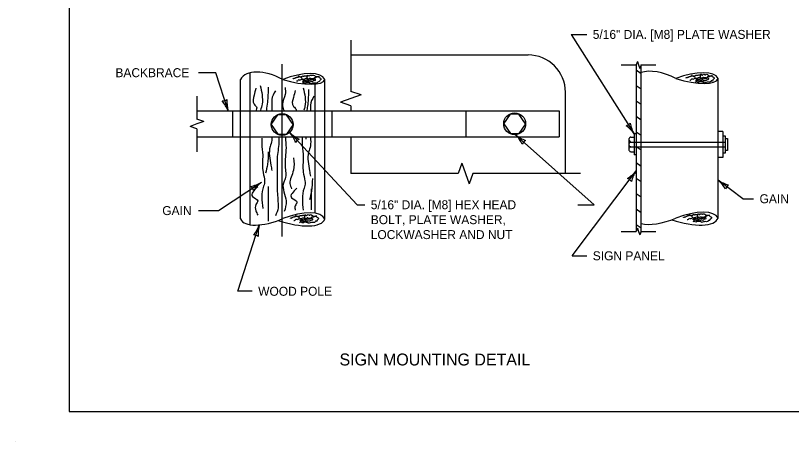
# Model space of a CAD drawing. Extents: x 49991.4 to 50021, y 49987.6 to 50011.4.
# Drawn here: x 49999.98 to 50005.17, y 49999.86 to 50002.71 of the extents above; entities that cross this region are included whole.
import ezdxf

# ---------------------------------------------------------------- set-up
doc = ezdxf.new("R2010")
doc.units = 0
for name, color, linetype in [('Level 1', 7, 'Continuous'), ('Level 2', 7, 'Continuous'), ('Level 3', 7, 'Continuous'), ('Level 4', 7, 'Continuous'), ('Level 5', 7, 'Continuous'), ('Level 6', 7, 'Continuous')]:
    doc.layers.add(name, color=color, linetype=linetype)

msp = doc.modelspace()

# ---------------------------------------------------------------- linework, layer by layer
at = {"layer": 'Level 1'}
for p, q in [((50002.2226, 50002.4506), (50003.4105, 50002.4506)), ((50001.5488, 50002.0757), (50001.5488, 50002.3308)), ((50004.1671, 50002.3252), (50004.1345, 50002.3481)), ((50001.4839, 50002.0757), (50001.4839, 50002.2867)), ((50002.0488, 50002.0757), (50002.0488, 50002.2867)), ((50004.6826, 50001.3581), (50004.6826, 50002.2926)), ((50001.9839, 50002.0757), (50001.9839, 50002.2554)), ((50004.1671, 50002.2217), (50004.1345, 50002.2446)), ((50003.6605, 50001.6566), (50003.6605, 50002.2006)), ((50004.1671, 50002.1183), (50004.1345, 50002.1412)), ((50001.1917, 50002.0757), (50003.6179, 50002.0757)), ((50001.4304, 50002.0757), (50001.4304, 50001.9014)), ((50002.0955, 50002.0757), (50002.0955, 50001.9014)), ((50002.9941, 50002.0757), (50002.9941, 50001.9014)), ((50003.6179, 50002.0757), (50003.6179, 50001.9014)), ((50001.6896, 50001.9851), (50001.7349, 50002.05)), ((50001.7913, 50002.05), (50001.7349, 50002.05)), ((50001.8366, 50001.9851), (50001.7913, 50002.05)), ((50003.2468, 50001.9897), (50003.2921, 50002.0546)), ((50003.3485, 50002.0546), (50003.2921, 50002.0546)), ((50003.3938, 50001.9897), (50003.3485, 50002.0546)), ((50004.1671, 50002.0148), (50004.1345, 50002.0377)), ((50001.6896, 50001.9851), (50001.7349, 50001.9202)), ((50001.8366, 50001.9851), (50001.7913, 50001.9202)), ((50003.2468, 50001.9897), (50003.2921, 50001.9248)), ((50003.3938, 50001.9897), (50003.3485, 50001.9248)), ((50001.7349, 50001.9202), (50001.7913, 50001.9202)), ((50003.2921, 50001.9248), (50003.3485, 50001.9248)), ((50004.1214, 50001.9215), (50004.1214, 50001.7823)), ((50004.1345, 50001.9215), (50004.1214, 50001.9215)), ((50004.1671, 50001.9114), (50004.1345, 50001.9343)), ((50004.716, 50001.9384), (50004.6826, 50001.9384)), ((50004.716, 50001.9384), (50004.716, 50001.7642)), ((50004.7325, 50001.9078), (50004.716, 50001.9078)), ((50004.7325, 50001.795), (50004.7325, 50001.9078)), ((50001.1917, 50001.9014), (50003.6179, 50001.9014)), ((50001.4839, 50001.3523), (50001.4839, 50001.9014)), ((50001.5488, 50001.3137), (50001.5488, 50001.9014)), ((50001.9211, 50001.8982), (50001.9219, 50001.886)), ((50001.9839, 50001.3907), (50001.9839, 50001.9014)), ((50002.0488, 50001.3523), (50002.0488, 50001.9014)), ((50004.0885, 50001.8114), (50004.0885, 50001.8912)), ((50004.0885, 50001.8676), (50004.1214, 50001.8676)), ((50004.0979, 50001.9004), (50004.1214, 50001.9004)), ((50004.0885, 50001.8351), (50004.1214, 50001.8351)), ((50004.098, 50001.8028), (50004.1214, 50001.8028)), ((50004.1671, 50001.8128), (50004.1345, 50001.8357)), ((50004.1345, 50001.7823), (50004.1214, 50001.7823)), ((50004.716, 50001.7642), (50004.6826, 50001.7642)), ((50004.716, 50001.795), (50004.7325, 50001.795)), ((50004.1671, 50001.7045), (50004.1345, 50001.7274)), ((50004.1671, 50001.601), (50004.1345, 50001.6239)), ((50004.1671, 50001.4976), (50004.1345, 50001.5205)), ((50004.1671, 50001.3944), (50004.1345, 50001.4173)), ((50004.1671, 50001.2904), (50004.1345, 50001.3133)), ((49999.9766, 49999.8624), (49999.9766, 49999.8624))]:
    msp.add_line(p, q, dxfattribs=at)
for points in [[(50008.6146, 50011.2628), (50000.3356, 50011.2628), (50000.3356, 50000.0624), (50008.6146, 50000.0624)], [(50004.7325, 50001.892), (50004.7452, 50001.892), (50004.7452, 50001.8102), (50004.7325, 50001.8102)]]:
    msp.add_lwpolyline(points, close=True, dxfattribs=at)
for points in [[(50004.1345, 50002.3834), (50004.1345, 50001.2689)], [(50004.1671, 50001.2689), (50004.1671, 50002.3834)]]:
    msp.add_lwpolyline(points, dxfattribs=at)
for centre in [(50003.3203, 50001.9897), (50001.7631, 50001.9851)]:
    msp.add_circle(centre, 0.0735, dxfattribs=at)
for centre, radius, start, end in [((50003.4105, 50002.2006), 0.25, 0, 90), ((50004.0978, 50001.8911), 0.0093, 89.3839, 179.3839), ((50004.0978, 50001.877), 0.00933, 180.3852, 270.3852), ((50004.0978, 50001.8583), 0.00929, 89.3617, 179.3617), ((50004.0979, 50001.8445), 0.00937, 181.6734, 271.6734), ((50004.0979, 50001.8257), 0.00942, 89.9897, 179.9897), ((50004.0976, 50001.8119), 0.00906, 182.8466, 272.8466)]:
    msp.add_arc(centre, radius, start, end, dxfattribs=at)
for centre, major_axis, ratio, start_param, end_param in [((50001.7031, 50002.169), (-0.2192, 0.1177), 0.537084, 4.712389, 6.283185), ((50001.8031, 50002.1916), (0.2457, 0.0951), 0.387082, 0, 1.570796), ((50004.3369, 50002.1748), (-0.2192, 0.1177), 0.537084, 4.712389, 5.832755), ((50004.4369, 50002.1975), (0.2457, 0.0951), 0.387082, 0, 1.570796), ((50001.7903, 50002.3655), (0.2585, -0.0788), 0.304673, 4.712389, 6.283185), ((50004.4241, 50002.3713), (0.2585, -0.0788), 0.304673, 4.712389, 6.283185), ((50001.8031, 50001.2572), (0.2457, 0.0951), 0.395997, 0, 1.56463), ((50004.4369, 50001.263), (0.2457, 0.0951), 0.387082, 0, 1.570796), ((50001.7235, 50001.4559), (-0.2396, -0.1036), 0.420526, 0, 1.570599), ((50001.7722, 50001.45), (0.2766, -0.0977), 0.384401, 4.720139, 6.283185), ((50004.3572, 50001.4617), (-0.2396, -0.1036), 0.429269, 0.492318, 1.564034), ((50004.406, 50001.4559), (0.2766, -0.0977), 0.384401, 4.732241, 6.283185)]:
    msp.add_ellipse(centre, major_axis=major_axis, ratio=ratio, start_param=start_param, end_param=end_param, dxfattribs=at)
for points in [[(50004.4697, 50002.2957), (50004.4697, 50002.2986), (50004.4755, 50002.2986), (50004.4798, 50002.3015), (50004.4842, 50002.3015), (50004.4885, 50002.3059), (50004.4928, 50002.3059), (50004.4986, 50002.3087), (50004.5029, 50002.3087), (50004.5115, 50002.3116), (50004.5202, 50002.3073), (50004.5245, 50002.3116), (50004.5303, 50002.3116), (50004.5346, 50002.3159), (50004.5418, 50002.3145), (50004.5461, 50002.3159), (50004.5505, 50002.3159), (50004.5563, 50002.3174), (50004.5605, 50002.3174), (50004.5663, 50002.3188), (50004.5735, 50002.3188), (50004.5735, 50002.3159), (50004.5778, 50002.3159), (50004.5836, 50002.3202), (50004.5923, 50002.3202), (50004.5966, 50002.3174), (50004.6009, 50002.3202), (50004.6124, 50002.3188), (50004.6226, 50002.3116), (50004.6341, 50002.3116), (50004.6398, 50002.3101), (50004.6441, 50002.3059), (50004.6528, 50002.3015), (50004.6571, 50002.2943), (50004.6557, 50002.2914), (50004.6485, 50002.2842), (50004.6427, 50002.2756), (50004.6398, 50002.2784), (50004.6341, 50002.2727), (50004.6268, 50002.2683), (50004.6182, 50002.2683), (50004.6023, 50002.2669), (50004.588, 50002.2626)], [(50004.562, 50002.29), (50004.5663, 50002.3001), (50004.5635, 50002.3073), (50004.5678, 50002.3159), (50004.5706, 50002.3231)], [(50001.836, 50002.2899), (50001.836, 50002.2928), (50001.8417, 50002.2928), (50001.846, 50002.2957), (50001.8504, 50002.2957), (50001.8547, 50002.3), (50001.859, 50002.3), (50001.8648, 50002.3029), (50001.8691, 50002.3029), (50001.8778, 50002.3057), (50001.8864, 50002.3015), (50001.8908, 50002.3057), (50001.8965, 50002.3057), (50001.9008, 50002.3101), (50001.9081, 50002.3087), (50001.9123, 50002.3101), (50001.9167, 50002.3101), (50001.9225, 50002.3115), (50001.9268, 50002.3115), (50001.9326, 50002.313), (50001.9398, 50002.313), (50001.9398, 50002.3101), (50001.9441, 50002.3101), (50001.9498, 50002.3144), (50001.9585, 50002.3144), (50001.9628, 50002.3115), (50001.9671, 50002.3144), (50001.9786, 50002.313), (50001.9888, 50002.3057), (50002.0003, 50002.3057), (50002.0061, 50002.3043), (50002.0104, 50002.3), (50002.019, 50002.2957), (50002.0234, 50002.2885), (50002.0219, 50002.2856), (50002.0147, 50002.2784), (50002.0089, 50002.2697), (50002.0061, 50002.2726), (50002.0003, 50002.2669), (50001.9931, 50002.2625), (50001.9844, 50002.2625), (50001.9686, 50002.2611), (50001.9542, 50002.2567)], [(50001.859, 50002.277), (50001.8677, 50002.2784), (50001.8735, 50002.2856), (50001.8821, 50002.2827), (50001.8908, 50002.287), (50001.9037, 50002.2885), (50001.9138, 50002.2914), (50001.934, 50002.2928), (50001.9426, 50002.2885), (50001.947, 50002.2957), (50001.9527, 50002.2942), (50001.9613, 50002.2928), (50001.97, 50002.2928), (50001.9715, 50002.2885), (50001.9772, 50002.2914), (50001.9816, 50002.2914), (50001.9844, 50002.2827), (50001.9816, 50002.2784), (50001.9772, 50002.2798), (50001.9715, 50002.277), (50001.9657, 50002.2712), (50001.9527, 50002.2741), (50001.9441, 50002.2654), (50001.9326, 50002.264), (50001.9268, 50002.264), (50001.9181, 50002.2597), (50001.9095, 50002.264), (50001.8965, 50002.2611)], [(50001.9138, 50002.2784), (50001.8965, 50002.2914), (50001.8908, 50002.2986), (50001.8763, 50002.3057), (50001.8705, 50002.3115)], [(50001.9023, 50002.2798), (50001.9081, 50002.2812), (50001.9181, 50002.2827), (50001.921, 50002.2798), (50001.9268, 50002.2827), (50001.934, 50002.2827), (50001.9368, 50002.2683), (50001.9311, 50002.2726), (50001.9268, 50002.2697), (50001.9196, 50002.2697), (50001.9123, 50002.2741), (50001.9037, 50002.2726), (50001.9008, 50002.2755), (50001.8994, 50002.2784)], [(50001.9282, 50002.2842), (50001.9326, 50002.2942), (50001.9297, 50002.3015), (50001.934, 50002.3101), (50001.9368, 50002.3173)], [(50001.9383, 50002.2683), (50001.9484, 50002.2625), (50001.9571, 50002.2625)], [(50001.9426, 50002.2784), (50001.9484, 50002.2842), (50001.9599, 50002.287), (50001.9729, 50002.2885), (50001.9816, 50002.3), (50001.9873, 50002.3), (50001.9916, 50002.3015), (50002.0017, 50002.3057), (50002.0119, 50002.3072)], [(50004.4928, 50002.2828), (50004.5015, 50002.2842), (50004.5072, 50002.2914), (50004.5159, 50002.2886), (50004.5245, 50002.2929), (50004.5375, 50002.2943), (50004.5476, 50002.2972), (50004.5678, 50002.2986), (50004.5764, 50002.2943), (50004.5808, 50002.3015), (50004.5865, 50002.3001), (50004.5951, 50002.2986), (50004.6038, 50002.2986), (50004.6053, 50002.2943), (50004.611, 50002.2972), (50004.6153, 50002.2972), (50004.6182, 50002.2886), (50004.6153, 50002.2842), (50004.611, 50002.2856), (50004.6053, 50002.2828), (50004.5995, 50002.277), (50004.5865, 50002.2799), (50004.5778, 50002.2713), (50004.5663, 50002.2698), (50004.5605, 50002.2698), (50004.5519, 50002.2655), (50004.5433, 50002.2698), (50004.5303, 50002.2669)], [(50004.5476, 50002.2842), (50004.5303, 50002.2972), (50004.5245, 50002.3044), (50004.5101, 50002.3116), (50004.5043, 50002.3174)], [(50004.536, 50002.2856), (50004.5418, 50002.2871), (50004.5519, 50002.2886), (50004.5548, 50002.2856), (50004.5605, 50002.2886), (50004.5678, 50002.2886), (50004.5706, 50002.2741), (50004.5649, 50002.2784), (50004.5605, 50002.2756), (50004.5533, 50002.2756), (50004.5461, 50002.2799), (50004.5375, 50002.2784), (50004.5346, 50002.2814), (50004.5332, 50002.2842)], [(50004.5721, 50002.2741), (50004.5822, 50002.2683), (50004.5908, 50002.2683)], [(50004.5764, 50002.2842), (50004.5822, 50002.29), (50004.5937, 50002.2929), (50004.6067, 50002.2943), (50004.6153, 50002.3059), (50004.6211, 50002.3059), (50004.6254, 50002.3073), (50004.6355, 50002.3116), (50004.6456, 50002.3131)], [(50001.5865, 50002.228), (50001.5746, 50002.1804), (50001.5746, 50002.1209), (50001.5924, 50002.0972), (50001.5879, 50002.0802)], [(50001.6165, 50002.247), (50001.6284, 50002.1221), (50001.6179, 50002.0802)], [(50001.67, 50002.2351), (50001.6641, 50002.134), (50001.657, 50002.0802)], [(50001.7829, 50002.2337), (50001.7829, 50002.1861), (50001.7651, 50002.1207), (50001.7731, 50002.0802)], [(50001.9038, 50002.2311), (50001.9157, 50002.1062), (50001.9091, 50002.0802)], [(50001.9398, 50002.219), (50001.9338, 50002.1179), (50001.9288, 50002.0802)], [(50001.7176, 50002.2113), (50001.6938, 50002.1519), (50001.6938, 50002.1281), (50001.6938, 50002.0802)], [(50001.8503, 50002.2133), (50001.8384, 50002.1657), (50001.8384, 50002.1062), (50001.8562, 50002.0825), (50001.8555, 50002.0802)], [(50001.9758, 50002.174), (50001.952, 50002.1146), (50001.952, 50002.0908), (50001.952, 50002.0802)], [(50001.6263, 50001.8945), (50001.6263, 50001.8569), (50001.6323, 50001.7796), (50001.6323, 50001.6785), (50001.6442, 50001.6191), (50001.6442, 50001.5893), (50001.6382, 50001.5715), (50001.6323, 50001.4229)], [(50001.6938, 50001.8982), (50001.6938, 50001.8784), (50001.6819, 50001.8368), (50001.6878, 50001.7119), (50001.6938, 50001.6763)], [(50001.7397, 50001.8982), (50001.7414, 50001.8784), (50001.7295, 50001.7714), (50001.7295, 50001.6941), (50001.7295, 50001.6168), (50001.7295, 50001.5633), (50001.7354, 50001.4563), (50001.7354, 50001.4266), (50001.7176, 50001.3731)], [(50001.7842, 50001.8982), (50001.7888, 50001.8294), (50001.7829, 50001.7046), (50001.7829, 50001.6213), (50001.771, 50001.5916), (50001.7888, 50001.4727), (50001.777, 50001.4013)], [(50001.8978, 50001.8982), (50001.8978, 50001.8446), (50001.9038, 50001.7674), (50001.9038, 50001.6663), (50001.9157, 50001.6069), (50001.9157, 50001.5771), (50001.9097, 50001.5593), (50001.9038, 50001.4106)], [(50001.952, 50001.8982), (50001.952, 50001.841), (50001.9401, 50001.7994), (50001.9461, 50001.6746), (50001.952, 50001.639)], [(50001.67, 50001.8011), (50001.6641, 50001.7179), (50001.6522, 50001.6584)], [(50001.8384, 50001.7614), (50001.8384, 50001.6782), (50001.8146, 50001.589), (50001.8265, 50001.5533)], [(50001.965, 50001.6224), (50001.959, 50001.5392), (50001.9471, 50001.4797)], [(50001.5991, 50001.5684), (50001.5634, 50001.503), (50001.5991, 50001.4733), (50001.5872, 50001.4495), (50001.5872, 50001.4079), (50001.5991, 50001.3782)], [(50001.67, 50001.5692), (50001.67, 50001.5336), (50001.67, 50001.4741), (50001.67, 50001.4087), (50001.67, 50001.379), (50001.67, 50001.3493), (50001.67, 50001.3374)], [(50001.8622, 50001.5593), (50001.8265, 50001.4939), (50001.8622, 50001.4641), (50001.8503, 50001.4404), (50001.8503, 50001.4102)], [(50001.9573, 50001.5533), (50001.9573, 50001.5177), (50001.9573, 50001.4582), (50001.9573, 50001.4132)], [(50004.4524, 50001.3617), (50004.4524, 50001.3646), (50004.4582, 50001.3646), (50004.4625, 50001.3674), (50004.4668, 50001.3674), (50004.4711, 50001.3718), (50004.4755, 50001.3718), (50004.4812, 50001.3747), (50004.4855, 50001.3747), (50004.4942, 50001.3775), (50004.5028, 50001.3732), (50004.5072, 50001.3775), (50004.5129, 50001.3775), (50004.5173, 50001.3819), (50004.5245, 50001.3804), (50004.5288, 50001.3819), (50004.5331, 50001.3819), (50004.5389, 50001.3833), (50004.5432, 50001.3833), (50004.549, 50001.3847), (50004.5562, 50001.3847), (50004.5562, 50001.3819), (50004.5605, 50001.3819), (50004.5663, 50001.3862), (50004.5749, 50001.3862), (50004.5793, 50001.3833), (50004.5836, 50001.3862), (50004.5951, 50001.3847), (50004.6052, 50001.3775), (50004.6167, 50001.3775), (50004.6225, 50001.3761), (50004.6268, 50001.3718), (50004.6354, 50001.3674), (50004.6398, 50001.3602), (50004.6383, 50001.3574), (50004.6311, 50001.3502), (50004.6253, 50001.3415), (50004.6225, 50001.3444), (50004.6167, 50001.3387), (50004.6095, 50001.3343), (50004.6008, 50001.3343), (50004.585, 50001.3329), (50004.5706, 50001.3285)], [(50004.5446, 50001.3559), (50004.549, 50001.366), (50004.5461, 50001.3732), (50004.5504, 50001.3819), (50004.5533, 50001.3891)], [(50001.8186, 50001.3558), (50001.8186, 50001.3588), (50001.8244, 50001.3588), (50001.8287, 50001.3616), (50001.833, 50001.3616), (50001.8373, 50001.366), (50001.8417, 50001.366), (50001.8475, 50001.3688), (50001.8518, 50001.3688), (50001.8604, 50001.3717), (50001.8691, 50001.3674), (50001.8734, 50001.3717), (50001.8791, 50001.3717), (50001.8835, 50001.3761), (50001.8907, 50001.3746), (50001.895, 50001.3761), (50001.8993, 50001.3761), (50001.9051, 50001.3775), (50001.9094, 50001.3775), (50001.9152, 50001.3789), (50001.9224, 50001.3789), (50001.9224, 50001.3761), (50001.9267, 50001.3761), (50001.9325, 50001.3803), (50001.9411, 50001.3803), (50001.9455, 50001.3775), (50001.9498, 50001.3803), (50001.9613, 50001.3789), (50001.9714, 50001.3717), (50001.9829, 50001.3717), (50001.9887, 50001.3703), (50001.993, 50001.366), (50002.0016, 50001.3616), (50002.006, 50001.3544), (50002.0046, 50001.3515), (50001.9974, 50001.3443), (50001.9916, 50001.3357), (50001.9887, 50001.3385), (50001.9829, 50001.3328), (50001.9757, 50001.3285), (50001.9671, 50001.3285), (50001.9512, 50001.327), (50001.9368, 50001.3227)], [(50001.8417, 50001.3429), (50001.8503, 50001.3443), (50001.8561, 50001.3515), (50001.8648, 50001.3487), (50001.8734, 50001.353), (50001.8863, 50001.3544), (50001.8965, 50001.3573), (50001.9166, 50001.3588), (50001.9253, 50001.3544), (50001.9296, 50001.3616), (50001.9353, 50001.3602), (50001.944, 50001.3588), (50001.9526, 50001.3588), (50001.9541, 50001.3544), (50001.9599, 50001.3573), (50001.9642, 50001.3573), (50001.9671, 50001.3487), (50001.9642, 50001.3443), (50001.9599, 50001.3458), (50001.9541, 50001.3429), (50001.9483, 50001.3371), (50001.9353, 50001.34), (50001.9267, 50001.3314), (50001.9152, 50001.3299), (50001.9094, 50001.3299), (50001.9008, 50001.3256), (50001.8921, 50001.3299), (50001.8791, 50001.327)], [(50001.8965, 50001.3443), (50001.8791, 50001.3573), (50001.8734, 50001.3645), (50001.859, 50001.3717), (50001.8532, 50001.3775)], [(50001.8849, 50001.3458), (50001.8907, 50001.3472), (50001.9008, 50001.3487), (50001.9036, 50001.3458), (50001.9094, 50001.3487), (50001.9166, 50001.3487), (50001.9195, 50001.3343), (50001.9138, 50001.3385), (50001.9094, 50001.3357), (50001.9022, 50001.3357), (50001.895, 50001.34), (50001.8863, 50001.3385), (50001.8835, 50001.3415), (50001.8821, 50001.3443)], [(50001.9108, 50001.3501), (50001.9152, 50001.3602), (50001.9123, 50001.3674), (50001.9166, 50001.3761), (50001.9195, 50001.3833)], [(50001.921, 50001.3343), (50001.9311, 50001.3285), (50001.9397, 50001.3285)], [(50001.9253, 50001.3443), (50001.9311, 50001.3501), (50001.9426, 50001.353), (50001.9556, 50001.3544), (50001.9642, 50001.366), (50001.97, 50001.366), (50001.9743, 50001.3674), (50001.9844, 50001.3717), (50001.9945, 50001.3732)], [(50004.4755, 50001.3487), (50004.4841, 50001.3502), (50004.4899, 50001.3574), (50004.4985, 50001.3545), (50004.5072, 50001.3588), (50004.5201, 50001.3602), (50004.5303, 50001.3632), (50004.5504, 50001.3646), (50004.559, 50001.3602), (50004.5634, 50001.3674), (50004.5691, 50001.366), (50004.5778, 50001.3646), (50004.5864, 50001.3646), (50004.5879, 50001.3602), (50004.5936, 50001.3632), (50004.598, 50001.3632), (50004.6008, 50001.3545), (50004.598, 50001.3502), (50004.5936, 50001.3516), (50004.5879, 50001.3487), (50004.5821, 50001.3429), (50004.5691, 50001.3459), (50004.5605, 50001.3372), (50004.549, 50001.3357), (50004.5432, 50001.3357), (50004.5345, 50001.3314), (50004.5259, 50001.3357), (50004.5129, 50001.3329)], [(50004.5303, 50001.3502), (50004.5129, 50001.3632), (50004.5072, 50001.3704), (50004.4928, 50001.3775), (50004.487, 50001.3833)], [(50004.5187, 50001.3516), (50004.5245, 50001.353), (50004.5345, 50001.3545), (50004.5374, 50001.3516), (50004.5432, 50001.3545), (50004.5504, 50001.3545), (50004.5533, 50001.3401), (50004.5475, 50001.3444), (50004.5432, 50001.3415), (50004.536, 50001.3415), (50004.5288, 50001.3459), (50004.5201, 50001.3444), (50004.5173, 50001.3473), (50004.5158, 50001.3502)], [(50004.5548, 50001.3401), (50004.5648, 50001.3343), (50004.5735, 50001.3343)], [(50004.559, 50001.3502), (50004.5648, 50001.3559), (50004.5763, 50001.3588), (50004.5893, 50001.3602), (50004.598, 50001.3718), (50004.6038, 50001.3718), (50004.6081, 50001.3732), (50004.6181, 50001.3775), (50004.6283, 50001.379)]]:
    msp.add_spline(points, degree=3, dxfattribs=at)
at = {"layer": 'Level 3'}
for p, q in [((50003.6983, 50002.5882), (50003.8036, 50002.5882)), ((50003.6983, 50002.5882), (50004.1214, 50001.9215)), ((50001.3176, 50002.3318), (50001.2027, 50002.3318)), ((50001.4007, 50002.0757), (50001.3176, 50002.3318)), ((50001.8133, 50001.9314), (50002.2654, 50001.4476)), ((50003.3256, 50001.9164), (50003.8532, 50001.4476)), ((50003.7058, 50001.1057), (50004.1345, 50001.6742)), ((50001.3362, 50001.4084), (50001.6252, 50001.598)), ((50004.8492, 50001.4879), (50004.6826, 50001.6123)), ((50004.8492, 50001.4879), (50004.921, 50001.4879)), ((50002.2654, 50001.4476), (50002.3164, 50001.4476)), ((50001.2027, 50001.4084), (50001.3362, 50001.4084)), ((50001.466, 50000.8681), (50001.6099, 50001.3127)), ((50003.7058, 50001.1057), (50003.8036, 50001.1057)), ((50001.5622, 50000.8681), (50001.466, 50000.8681))]:
    msp.add_line(p, q, dxfattribs=at)
msp.add_lwpolyline([(50003.7431, 50001.4476), (50003.7431, 50001.4476), (50003.8532, 50001.4476)], dxfattribs=at)
for centre, radius, start, end in [((50001.3611, 50002.1977), 0.0548, 270.1162, 305.8385), ((50001.1829, 50001.993), 0.233, 20.8047, 40.0545), ((50001.6148, 50002.1356), 0.2223, 175.4334, 195.6169), ((50004.0527, 50002.0298), 0.0548, 284.5388, 320.2611), ((50003.9311, 50001.7871), 0.233, 35.2273, 54.4771), ((50004.3139, 50002.0328), 0.2223, 189.856, 210.0395), ((50001.6447, 50001.7864), 0.2223, 20.5178, 40.7013), ((50001.9755, 50002.0987), 0.233, 225.8891, 245.1389), ((50003.1712, 50001.7564), 0.2223, 25.8372, 46.0207), ((50003.4715, 50002.098), 0.233, 231.2085, 250.4583), ((50001.9008, 50001.8378), 0.0548, 115.2006, 150.9229), ((50003.4214, 50001.8313), 0.0548, 120.52, 156.2423), ((50003.9627, 50001.8153), 0.2223, 300.4378, 320.6213), ((50004.3272, 50001.5433), 0.233, 145.8091, 165.059), ((50001.511, 50001.7888), 0.2223, 280.7278, 300.9113), ((50001.7625, 50001.4098), 0.233, 126.0991, 145.3489), ((50004.0573, 50001.5718), 0.0548, 35.1206, 70.843), ((50004.5423, 50001.4398), 0.2223, 30.7228, 50.9064), ((50004.8125, 50001.8057), 0.233, 236.0941, 255.344), ((50001.518, 50001.5277), 0.0548, 15.4106, 51.133), ((50004.7853, 50001.5357), 0.0548, 125.4057, 161.128), ((50001.4013, 50001.3898), 0.2223, 319.5225, 339.7061), ((50001.8348, 50001.252), 0.233, 164.8938, 184.1437), ((50001.5704, 50001.1907), 0.0548, 54.2054, 89.9277)]:
    msp.add_arc(centre, radius, start, end, dxfattribs=at)
at = {"layer": 'Level 4'}
for p, q in [((50001.4839, 50001.9014), (50001.4839, 50002.0757)), ((50001.5488, 50001.9014), (50001.5488, 50002.0757)), ((50001.9839, 50001.9014), (50001.9839, 50002.0757)), ((50002.0488, 50001.9014), (50002.0488, 50002.0757)), ((50004.1214, 50001.8668), (50004.7325, 50001.8668)), ((50004.1214, 50001.8353), (50004.7325, 50001.8353))]:
    msp.add_line(p, q, dxfattribs=at)
at = {"layer": 'Level 5'}
msp.add_line((50001.7631, 50001.2343), (50001.7631, 50002.3884), dxfattribs=at)
at = {"layer": 'Level 6'}
for p, q in [((50002.2226, 50002.5506), (50002.2226, 50002.2069)), ((50004.0345, 50002.3834), (50004.1346, 50002.3834)), ((50004.1427, 50002.4063), (50004.1346, 50002.3834)), ((50004.1427, 50002.4063), (50004.1508, 50002.3834)), ((50004.1508, 50002.3834), (50004.1589, 50002.3605)), ((50004.167, 50002.3834), (50004.1589, 50002.3605)), ((50004.167, 50002.3834), (50004.2671, 50002.3834)), ((50001.1917, 50002.1757), (50001.1917, 50002.0209)), ((50002.2911, 50002.1826), (50002.2226, 50002.2069)), ((50002.2911, 50002.1826), (50002.2226, 50002.1583)), ((50002.2226, 50002.1583), (50002.1541, 50002.134)), ((50002.2226, 50002.1097), (50002.1541, 50002.134)), ((50002.2226, 50002.1097), (50002.2226, 50002.0757)), ((50001.2374, 50002.0047), (50001.1917, 50002.0209)), ((50001.1917, 50001.9885), (50001.146, 50001.9723)), ((50001.1917, 50001.9561), (50001.146, 50001.9723)), ((50001.2374, 50002.0047), (50001.1917, 50001.9885)), ((50001.1917, 50001.9561), (50001.1917, 50001.8014)), ((50002.2226, 50001.9014), (50002.2226, 50001.6566)), ((50002.9672, 50001.7251), (50002.9429, 50001.6566)), ((50002.9672, 50001.7251), (50002.9915, 50001.6566)), ((50002.9429, 50001.6566), (50002.2226, 50001.6566)), ((50002.9915, 50001.6566), (50003.0158, 50001.5881)), ((50003.0401, 50001.6566), (50003.0158, 50001.5881)), ((50003.7605, 50001.6566), (50003.0401, 50001.6566)), ((50004.1427, 50001.2918), (50004.1346, 50001.2689)), ((50004.1427, 50001.2918), (50004.1508, 50001.2689)), ((50004.0345, 50001.2689), (50004.1346, 50001.2689)), ((50004.1508, 50001.2689), (50004.1589, 50001.246)), ((50004.167, 50001.2689), (50004.1589, 50001.246)), ((50004.167, 50001.2689), (50004.2671, 50001.2689))]:
    msp.add_line(p, q, dxfattribs=at)

# ---------------------------------------------------------------- texts
at = {"layer": 'Level 2'}
for s, height, p in [('5/16" DIA. [M8] PLATE WASHER', 0.06, (50003.8436, 50002.5582)), ('BACKBRACE', 0.06, (50000.6459, 50002.3018)), ('GAIN', 0.06, (50004.961, 50001.4579)), ('GAIN', 0.06, (50000.9597, 50001.3784)), ('5/16" DIA. [M8] HEX HEAD', 0.06, (50002.3564, 50001.4176)), ('BOLT, PLATE WASHER,', 0.06, (50002.3564, 50001.3176)), ('LOCKWASHER AND NUT', 0.06, (50002.3564, 50001.2176)), ('SIGN PANEL', 0.06, (50003.8436, 50001.0757)), ('WOOD POLE', 0.06, (50001.6022, 50000.8381)), ('SIGN MOUNTING DETAIL', 0.08, (50002.1471, 50000.3713))]:
    msp.add_text(s, height=height, dxfattribs=at).set_placement(p)

doc.saveas('drawing.dxf')
